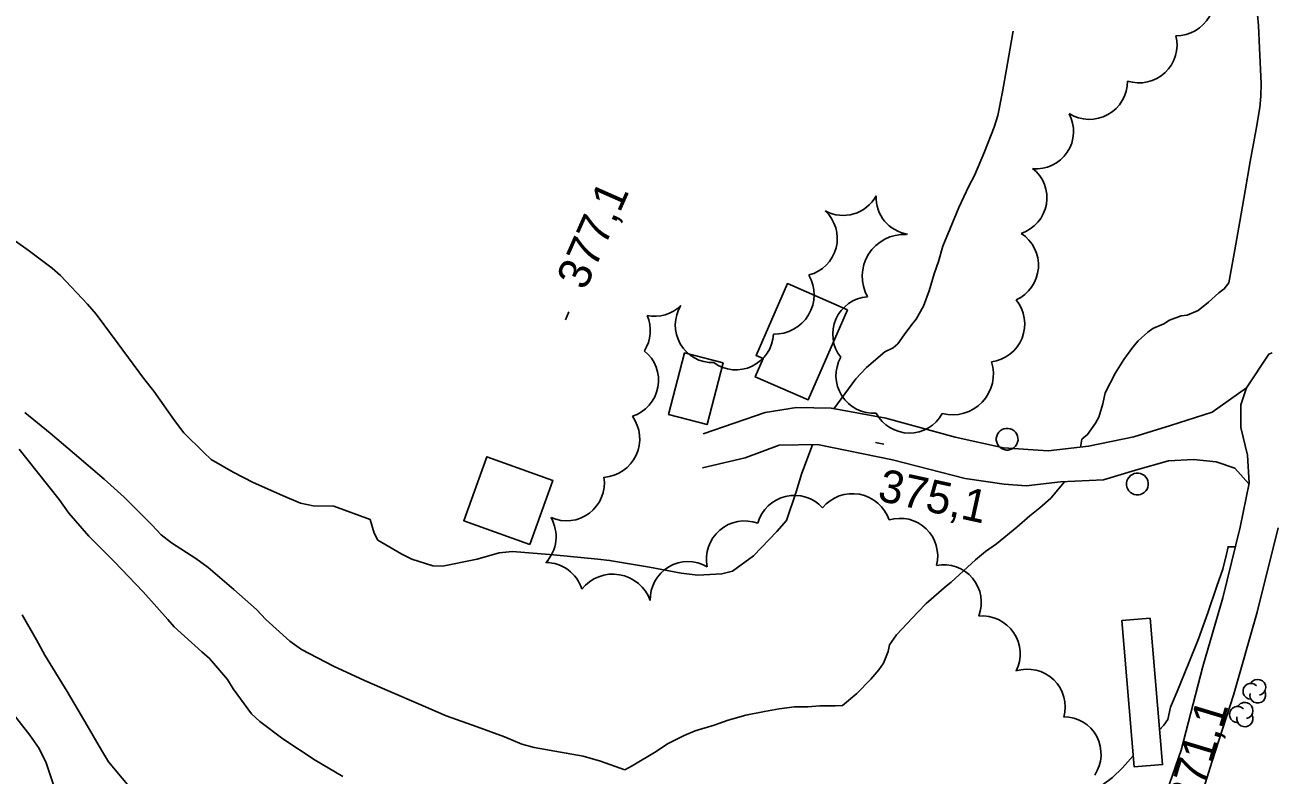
# Model space of a CAD drawing. Extents: x 287698 to 290158, y 5234163 to 5237182.
# Drawn here: x 288812.3 to 288926.6, y 5234673.3 to 5234742.3 of the extents above; entities that cross this region are included whole.
import ezdxf

# ---------------------------------------------------------------- set-up
doc = ezdxf.new("R2010")
doc.units = 0
for name, color, linetype in [('Niveau 1', 7, 'Continuous'), ('Niveau 19', 7, 'Continuous'), ('Niveau 2', 7, 'Continuous'), ('Niveau 21', 7, 'Continuous'), ('Niveau 3', 7, 'Continuous'), ('Niveau 31', 7, 'Continuous'), ('Niveau 36', 7, 'Continuous'), ('Niveau 44', 7, 'Continuous')]:
    doc.layers.add(name, color=color, linetype=linetype)

msp = doc.modelspace()

# ---------------------------------------------------------------- linework, layer by layer
at = {"layer": 'Niveau 1'}
msp.add_lwpolyline([(288842.23, 5234645.37), (288841.64, 5234645.53), (288840.76, 5234645.97), (288839.88, 5234646.81), (288837.85, 5234649.47), (288837.15, 5234650.86), (288835.8, 5234654.01), (288834.62, 5234656.82), (288833.96, 5234658.08), (288831.64, 5234661.11), (288830.36, 5234662.62), (288828.59, 5234664.43), (288826.7, 5234666.56), (288826.05, 5234667.44), (288823.92, 5234670.08), (288822.43, 5234671.55), (288819.93, 5234674.57), (288819.28, 5234675.64), (288817.76, 5234678.26), (288816.14, 5234681.01), (288814.08, 5234684.37), (288813.31, 5234685.77), (288812.01, 5234688.08)], dxfattribs=at)
at = {"layer": 'Niveau 19'}
for points in [[(288874.51, 5234704.71), (288880.21, 5234706.65), (288883.08, 5234707.12), (288886.26, 5234707.06), (288891.29, 5234706.13), (288897.67, 5234704.38), (288902.08, 5234703.4), (288906.2, 5234703.14), (288909.91, 5234703.56), (288914.06, 5234704.43), (288917.43, 5234705.46), (288921.24, 5234706.68), (288924.4, 5234708.94)], [(288915.75, 5234667.94), (288918.42, 5234675.63), (288920.39, 5234683.32), (288922.23, 5234689.64), (288923.82, 5234696.12), (288924.64, 5234700.16), (288924.49, 5234702.75), (288923.88, 5234705.29), (288923.88, 5234707.38), (288924.4, 5234708.94)], [(288924.63, 5234700.11), (288923.34, 5234701.54), (288921.62, 5234702.13), (288919.55, 5234702.35), (288917.25, 5234702.21), (288914.21, 5234701.36), (288911.27, 5234700.48), (288907.34, 5234700.28), (288904.17, 5234699.92), (288902.15, 5234700.08), (288898.58, 5234700.6), (288891.9, 5234702.31), (288885.02, 5234703.71), (288881.51, 5234703.65), (288878.37, 5234702.5), (288874.45, 5234701.59)], [(288927.31, 5234696.06), (288925.39, 5234688.31), (288923.22, 5234680.69), (288921.23, 5234674.52), (288918.91, 5234667.07), (288916.46, 5234660.21), (288913.84, 5234653.53), (288910.97, 5234646.36), (288908.79, 5234639.53), (288907.08, 5234632.14), (288906.08, 5234626.46), (288905.95, 5234621.11), (288906.7, 5234616.26), (288908.34, 5234612.68), (288910.7, 5234607.62), (288913.65, 5234602.85), (288916.84, 5234597.86), (288920.11, 5234592.8), (288924.01, 5234587.09), (288927.85, 5234582.23)]]:
    msp.add_lwpolyline(points, dxfattribs=at)
at = {"layer": 'Niveau 2'}
for points in [[(288925.42, 5234743.19), (288925.51, 5234742.22), (288925.59, 5234740.15), (288925.75, 5234736.89), (288925.73, 5234735.74), (288925.63, 5234734.7), (288925.28, 5234732.71), (288924.75, 5234729.72), (288924.28, 5234727.04), (288923.78, 5234724.2), (288923.32, 5234721.6), (288922.79, 5234718.59), (288922.36, 5234718.02), (288921.85, 5234717.66), (288920.92, 5234716.79), (288919.96, 5234716.04), (288918.95, 5234715.61), (288918.41, 5234715.54), (288917.33, 5234715.15), (288916.8, 5234714.81), (288915.81, 5234714.38), (288915.35, 5234714.05), (288914.45, 5234713.24), (288913.98, 5234712.67), (288913.14, 5234711.54), (288912.37, 5234710.31), (288911.44, 5234708.47), (288911.2, 5234707.47), (288910.84, 5234706.22), (288910.54, 5234705.68), (288909.81, 5234704.63), (288909.3, 5234704.21)], [(288902.98, 5234741.7), (288902.96, 5234741.56), (288902.46, 5234738.72), (288902, 5234736.12), (288901.56, 5234733.95), (288901.23, 5234732.89), (288900.36, 5234730.6), (288899.43, 5234728.43), (288898.91, 5234727.47), (288897.98, 5234725.5), (288897.21, 5234723.56), (288896.52, 5234721.96), (288896.13, 5234720.54), (288895.72, 5234719.4), (288895.26, 5234717.83), (288894.74, 5234716.44), (288894.08, 5234715.24), (288893.67, 5234714.76), (288892.97, 5234713.81), (288892.38, 5234712.98), (288891.95, 5234712.61)], [(288843.94, 5234696.83), (288840.61, 5234698.04), (288838.71, 5234698.1), (288837.54, 5234698.33), (288835.89, 5234699.02), (288833.2, 5234700.24), (288831.37, 5234701.17), (288829.35, 5234702.35), (288828.64, 5234703.01), (288826.85, 5234704.8), (288825.98, 5234705.93), (288824.08, 5234708.63), (288823.13, 5234709.83), (288820.81, 5234712.96), (288818.79, 5234715.7), (288817.99, 5234716.61), (288815.51, 5234719.25), (288814.75, 5234719.93), (288812.55, 5234721.59), (288809.46, 5234723.76)], [(288891.95, 5234712.61), (288891.2, 5234712.23), (288889.53, 5234710.8), (288888.54, 5234709.77), (288886.52, 5234707.01)], [(288867.34, 5234673.84), (288865.11, 5234674.63), (288863.49, 5234675.09), (288861.95, 5234675.36), (288859.01, 5234675.87), (288857.86, 5234676.19), (288856.27, 5234676.86), (288853.78, 5234677.77), (288850.94, 5234678.8), (288848.61, 5234679.79), (288845.76, 5234681.02), (288843.44, 5234682.03), (288840.57, 5234683.34), (288837.64, 5234684.88), (288836.57, 5234685.66), (288834.38, 5234687.63), (288833.5, 5234688.55), (288831.44, 5234690.41), (288829.09, 5234692.42), (288827.95, 5234693.26), (288825.72, 5234694.69), (288824.76, 5234695.42), (288823.92, 5234696.35), (288821.36, 5234698.89), (288819.54, 5234700.52), (288816.82, 5234702.85), (288814.58, 5234704.75), (288812.25, 5234706.65)], [(288909.3, 5234704.21), (288909.16, 5234703.47)], [(288841.44, 5234673.22), (288838.9, 5234674.71), (288835.93, 5234676.68), (288833.81, 5234678.28), (288833.06, 5234678.98), (288831.36, 5234681.27), (288830.86, 5234682.12), (288829.21, 5234684.07), (288828.5, 5234684.67), (288825.96, 5234686.98), (288825.38, 5234687.65), (288823.11, 5234690.19), (288820.45, 5234692.96), (288818.11, 5234695.3), (288816.3, 5234697.4), (288815.39, 5234698.67), (288813.37, 5234701.2), (288811.72, 5234703.3)], [(288884.55, 5234703.7), (288883.58, 5234701.08), (288883.05, 5234699.37)], [(288883.05, 5234699.37), (288882.17, 5234696.74), (288881.28, 5234695.73), (288879.14, 5234693.49), (288877.23, 5234692.08), (288876.25, 5234691.85), (288874.02, 5234691.7), (288872.5, 5234691.9), (288869.58, 5234692.46), (288865.93, 5234693.07), (288864.84, 5234693.18), (288860.78, 5234693.58), (288857.02, 5234693.89), (288855.8, 5234693.76), (288853.78, 5234693.18), (288850.58, 5234692.54), (288849.69, 5234692.57), (288847.79, 5234693.18), (288846.87, 5234693.65), (288844.66, 5234694.93), (288844.32, 5234695.56), (288843.94, 5234696.83)], [(288907.71, 5234700.3), (288906.43, 5234698.79), (288905.44, 5234697.9), (288904.51, 5234697.17), (288903.31, 5234696.12), (288901.44, 5234694.59), (288900.44, 5234693.88), (288899.53, 5234693.12), (288897.29, 5234691.06), (288896.87, 5234690.72), (288894.99, 5234689.11), (288894.22, 5234688.31), (288892.27, 5234686.23), (288891.63, 5234685.32), (288891.5, 5234684.71), (288891.07, 5234683.64), (288890.64, 5234683.01), (288889.9, 5234682.16), (288888.64, 5234680.84), (288887.3, 5234679.74), (288886.64, 5234679.72), (288885.22, 5234679.7), (288884.13, 5234679.6), (288882.9, 5234679.6), (288881.5, 5234679.43), (288880.15, 5234679.2), (288878.45, 5234678.84), (288876.82, 5234678.39), (288875.52, 5234677.94), (288873.79, 5234677.42), (288872.78, 5234676.98), (288871.26, 5234676.2), (288870.2, 5234675.52), (288867.99, 5234674.2), (288867.34, 5234673.84)], [(288923.38, 5234694.31), (288922.71, 5234694.33), (288922.58, 5234693.64), (288922.23, 5234692.28), (288921.69, 5234690.7), (288920.84, 5234688.24), (288919.99, 5234685.87), (288919.11, 5234683.66), (288918.04, 5234681.03), (288917.44, 5234679.57), (288917.18, 5234678.45), (288916.81, 5234677.93), (288916.43, 5234677.51)], [(288819.45, 5234665.52), (288817.44, 5234667.97), (288815.48, 5234670.59), (288815.2, 5234671.44), (288814.21, 5234674.48), (288813.55, 5234675.78), (288812.72, 5234677.02), (288810.54, 5234679.81)], [(288914.01, 5234675.12), (288913.02, 5234674), (288912.11, 5234673.11), (288911.16, 5234672.41), (288910.19, 5234671.53), (288909.72, 5234670.95), (288909.1, 5234669.94), (288908.37, 5234668.99), (288907.98, 5234668.48)]]:
    msp.add_lwpolyline(points, dxfattribs=at)
at = {"layer": 'Niveau 21'}
msp.add_lwpolyline([(288924.4, 5234708.94), (288926.45, 5234712.01), (288926.77, 5234712.15)], dxfattribs=at)
at = {"layer": 'Niveau 3'}
for p, q in [((288861.87, 5234715.19), (288862.19, 5234715.92)), ((288890.34, 5234703.89), (288891.12, 5234703.75))]:
    msp.add_line(p, q, dxfattribs=at)
at = {"layer": 'Niveau 31'}
for points in [[(288887.76, 5234716.11), (288884.15, 5234707.82), (288879.3, 5234709.93), (288880.04, 5234711.63), (288879.38, 5234711.91), (288882.25, 5234718.5)], [(288876.36, 5234711.22), (288874.89, 5234705.56), (288871.34, 5234706.48), (288872.81, 5234712.14)], [(288858.6, 5234694.53), (288852.54, 5234696.71), (288854.66, 5234702.6), (288860.72, 5234700.42)], [(288915.56, 5234687.76), (288916.7, 5234674.31), (288914.1, 5234674.09), (288912.96, 5234687.54)]]:
    msp.add_lwpolyline(points, close=True, dxfattribs=at)
at = {"layer": 'Niveau 36'}
for centre in [(288902.43, 5234704.21), (288914.39, 5234700.09)]:
    msp.add_ellipse(centre, major_axis=(0.472, 0.882), ratio=0.999983, dxfattribs=at)
at = {"layer": 'Niveau 44'}
for centre, radius, start, end in [((288917.96, 5234744.77), 3.49, 269.4965, 31.5021), ((288892.99, 5234719.16), 3.87, 87.0734, 208.8747), ((288866.23, 5234688.17), 3.64, 19.4186, 141.4201), ((288924.81, 5234681.05), 0.727, 44.1154, 269.804), ((288925.44, 5234680.69), 0.727, 166.9369, 29.6212), ((288925.44, 5234681.41), 0.727, 282.2692, 149.7263), ((288924.25, 5234679.27), 0.747, 282.2692, 149.7263), ((288923.6, 5234678.9), 0.747, 44.1154, 269.804), ((288924.25, 5234678.53), 0.747, 166.9369, 29.6212)]:
    msp.add_arc(centre, radius, start, end, dxfattribs=at)
for centre, major_axis, ratio, start_param, end_param in [((288914.54, 5234740.44), (-0.82, 3.39), 0.999984, 2.595802, 4.718983), ((288909.97, 5234737.11), (1.71, -3.07), 0.999469, 5.220002, 7.345005), ((288905.08, 5234732.49), (2.78, -2.04), 0.999344, 5.252632, 7.408363), ((288902.64, 5234726.39), (3.44, 0.13), 0.999488, 4.991667, 7.149707), ((288887.36, 5234728.23), (2.89, 1.9), 0.999985, 3.637024, 5.200762), ((288893.84, 5234726.45), (1.13, -3.26), 0.999939, 4.34554, 5.790569), ((288883.38, 5234722.65), (0.85, 3.35), 0.999985, 3.636814, 5.787964), ((288901.8, 5234720.19), (-2.91, 1.95), 0.999984, 2.591375, 4.721079), ((288881.09, 5234717.49), (3.11, -1.86), 0.999821, 5.217062, 7.344166), ((288870.04, 5234718.95), (3.3, -1), 0.999939, 4.809785, 5.789634), ((288875.41, 5234714.69), (1.72, -2.99), 0.999863, 3.637261, 5.787517), ((288889.87, 5234713.86), (-1.39, -3.16), 0.999985, 3.634736, 5.790042), ((288900.55, 5234714.8), (3.12, -1.58), 0.999514, 5.306992, 7.437877), ((288866.21, 5234714.18), (-1.68, 3.02), 0.999939, 3.635633, 4.618052), ((288877.53, 5234714.03), (3.11, 1.49), 0.999985, 3.636183, 5.788596), ((288866.96, 5234709.61), (0.62, 3.41), 0.99976, 3.634331, 5.790447), ((288890.17, 5234710.05), (1.85, -2.92), 0.999863, 3.637044, 5.787734), ((288897.42, 5234710.2), (2.72, -2.58), 0.999438, 5.217034, 7.348431), ((288865.16, 5234704.23), (3.21, -1.49), 0.999995, 5.219829, 7.346835), ((288893.45, 5234708.21), (3.44, -0.02), 0.999939, 3.633862, 5.790916), ((288862, 5234700.16), (2.33, 2.57), 0.992312, 3.449435, 5.603005), ((288888.22, 5234695.62), (0.72, 3.51), 0.994554, 5.244466, 7.360536), ((288882.91, 5234695.52), (-0.84, 3.43), 0.994919, 5.217161, 7.335188), ((288892.57, 5234693.45), (2.41, 2.55), 0.987261, 5.223634, 7.330781), ((288857.57, 5234695.25), (0.29, 3.45), 0.99644, 4.03321, 5.329079), ((288878.33, 5234693.19), (-2.29, 2.66), 0.998635, 5.222023, 7.344302), ((288860.07, 5234689.45), (-3.4, 0.68), 0.988134, 3.63576, 4.907236), ((288873.14, 5234689.48), (-1.77, 3), 0.999978, 5.222666, 7.350394), ((288896.57, 5234689.19), (2.74, 2.17), 0.995918, 5.249821, 7.369085), ((288900.13, 5234684.48), (2.98, 1.82), 0.998351, 5.268119, 7.39303), ((288904.3, 5234679.61), (-2.5, 2.41), 0.99661, 3.635534, 5.789244), ((288907.62, 5234675.24), (1.81, 2.95), 0.989285, 4.676413, 6.833871)]:
    msp.add_ellipse(centre, major_axis=major_axis, ratio=ratio, start_param=start_param, end_param=end_param, dxfattribs=at)

# ---------------------------------------------------------------- texts
at = {"layer": 'Niveau 3'}
for s, rotation, p in [('377,1', 66.1217, (288863.7, 5234717.8)), ('375,1', 347.6494, (288890.43, 5234698.6)), ('371,1', 73.1538, (288919.86, 5234670.06))]:
    msp.add_text(s, height=3, rotation=rotation, dxfattribs=at).set_placement(p)

doc.saveas('drawing.dxf')
